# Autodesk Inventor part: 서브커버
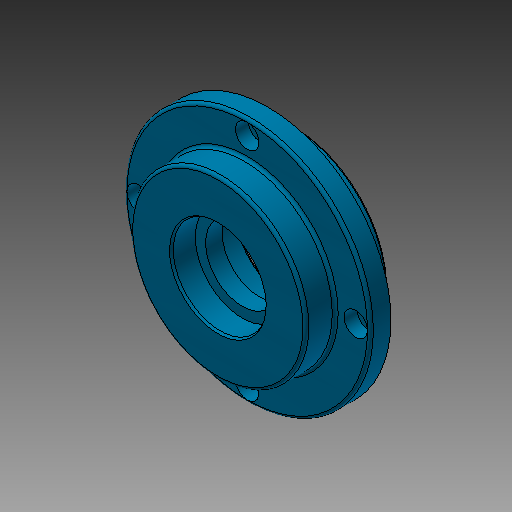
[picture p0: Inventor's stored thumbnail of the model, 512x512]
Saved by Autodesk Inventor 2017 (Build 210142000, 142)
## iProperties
Created: 2018-09
Part Number: 서브커버
Material: 알루미늄 6061
Document SubType Name: Modeling
Designer: mduedu
Density: 1 g/cm^3
Appearance: 하늘색 중간
Author: mduedu
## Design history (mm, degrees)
sketch "스케치1"
  geometry: C1 r 42 at (0, 0); 1 further point
  constraints: 1 centre point, 1 coincident
  dimensions: "d34" = 84 diameter of C1
extrude "돌출1" new body sketch "스케치1" distance "d2" = 7; taper "d3" = 0 deg
sketch "스케치2"
  geometry: C1 r 30 at (0, 0); 1 further point
  constraints: 1 centre point, 1 coincident
  dimensions: "d4" = 60 diameter of C1
extrude "돌출2" join sketch "스케치2" distance "d5" = 10; taper "d6" = 0 deg
sketch "스케치3"
  geometry: C1 r 32.5 at (0, 0); 1 further point
  constraints: 1 centre point, 1 coincident
  dimensions: "d7" = 65 diameter of C1
extrude "돌출3" join sketch "스케치3" distance "d8" = 9; taper "d9" = 0 deg
sketch "스케치4"
  geometry: L1 (-32.5, -9)-(32.5, -9) reference; L2 (30, 17)-(-30, 17) reference; L3 (0, 17)-(0, -9); L4 (0, -9)-(20, -9); L5 (20, -9)-(20, 3); L6 (20, 3)-(0, 3); L7 (0, 3)-(0, -9); L8 (0, 3)-(12.5, 3); L9 (12.5, 3)-(12.5, 8.7); L10 (12.5, 8.7)-(0, 8.7); L11 (0, 8.7)-(0, 3); L12 (0, 8.7)-(16, 8.7); L13 (16, 8.7)-(16, 17); L14 (16, 17)-(0, 17); L15 (0, 17)-(0, 8.7); 1 further point
  constraints: 26 end point, 6 parallel, 3 horizontal, 3 perpendicular, 2 midpoint, 1 point on line
  dimensions: "d10" = 12 distance of L4.end L5.end; "d12" = 8.3 distance of L12.end L13.end; "d13" = 32 diameter of L13 L3; "d14" = 25 diameter of L9 L3; "d15" = 40 diameter of L5 L3
revolve "회전1" sketch "스케치4" stored, may be unused: angle "d16" = 90 deg
fillet "모깎기2" dims "d18" = 1
fillet "모깎기3" dims "d19" = 1
chamfer "모따기1" distance "d20" = 0.8; stored, may be unused: second distance "d21" = 2, angle "d22" = 30 deg
chamfer "모따기2" distance "d23" = 1; stored, may be unused: second distance "d24" = 2, angle "d25" = 30 deg
fillet "모깎기4" dims "d26" = 0.3
sketch "스케치5" dims "d35" = 74
  geometry: 3 further points
  constraints: 2 vertical alignment, 1 coincident, 2 other
hole "구멍1" sketch "스케치5" at (0, 37) diameter "d27" = 4.5; stored, may be unused: countersink angle "d31" = 90 deg, drill point angle "d33" = 118 deg; dims "d28" = 6, "d29" = 8, "d30" = 4.4, "d32" = 8
node "솔리드1"
pattern_circular "원형 패턴1" dims angle "d37" = 360 deg
